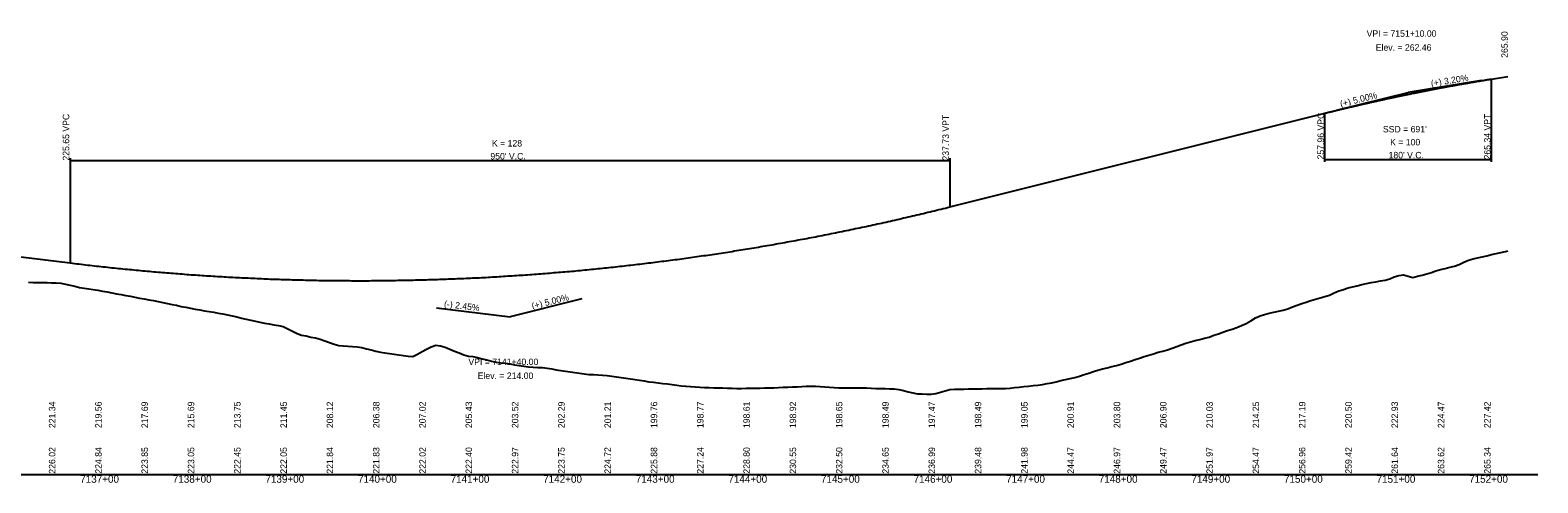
# Model space of a CAD drawing. Extents: x 1838386 to 1955906, y 719739 to 834437.
# Drawn here: x 1897153 to 1898782, y 770980 to 771469 of the extents above; entities that cross this region are included whole.
import ezdxf

# ---------------------------------------------------------------- set-up
doc = ezdxf.new("R2010")
doc.units = 0
for name, color, linetype in [('RD_DDB_GradeTX', 7, 'Continuous'), ('RD_DDB_Profile_EX', 7, 'Continuous'), ('RD_DDB_Profile_Lbl', 7, 'Continuous'), ('RD_DDB_Profile_PR', 7, 'Continuous'), ('RD_DDB_StaTX', 7, 'Continuous'), ('RD_DDB_StripGrade', 7, 'Continuous'), ('RD_DDB_VCLbl', 7, 'Continuous'), ('RD_GPK_Profile_Cell', 7, 'Continuous')]:
    doc.layers.add(name, color=color, linetype=linetype)

msp = doc.modelspace()

# ---------------------------------------------------------------- linework, layer by layer
at = {"layer": 'RD_DDB_GradeTX'}
for p, q in [((1898720.6, 771414.1), (1898641.6, 771401.4)), ((1898564, 771382.1), (1898641.6, 771401.4)), ((1897592.2, 771168.9), (1897671.6, 771159.1)), ((1897749.2, 771178.5), (1897671.6, 771159.1))]:
    msp.add_line(p, q, dxfattribs=at)
at = {"layer": 'RD_DDB_Profile_EX'}
for points in [[(1898226.6, 771083.9), (1898231.6, 771084.4), (1898236.6, 771084.9), (1898241.6, 771085.4), (1898246.6, 771086.3), (1898251.6, 771087.2), (1898256.6, 771088.1), (1898261.6, 771089.2), (1898266.6, 771090.3), (1898271.6, 771091.4), (1898276.6, 771092.6), (1898281.6, 771093.7), (1898286.6, 771095.2), (1898291.6, 771096.9), (1898296.6, 771098.5), (1898301.6, 771100), (1898306.6, 771101.5), (1898311.6, 771102.9), (1898316.6, 771104.2), (1898321.6, 771105.4), (1898326.6, 771106.6), (1898331.6, 771108.2), (1898336.6, 771109.9), (1898341.6, 771111.5), (1898346.6, 771113), (1898351.6, 771114.5), (1898356.6, 771116.2), (1898361.6, 771117.8), (1898366.6, 771119.4), (1898371.6, 771120.9), (1898376.6, 771122.3), (1898381.6, 771123.7), (1898386.6, 771125.4), (1898391.6, 771127.2), (1898396.6, 771128.9), (1898401.6, 771130.6), (1898406.6, 771132.2), (1898411.6, 771133.6), (1898416.6, 771134.8), (1898421.6, 771136), (1898426.6, 771137.4), (1898431.6, 771139.3), (1898436.6, 771141), (1898441.6, 771142.7), (1898446.6, 771144.4), (1898451.6, 771145.9), (1898456.6, 771147.7), (1898461.6, 771149.9), (1898466.6, 771152), (1898471.6, 771154.9), (1898476.6, 771158.1), (1898481.6, 771160.4), (1898486.6, 771161.7), (1898491.6, 771163), (1898496.6, 771164.2), (1898501.6, 771165.4), (1898506.6, 771166.5), (1898511.6, 771167.9), (1898516.6, 771169.9), (1898521.6, 771171.8), (1898526.6, 771173.5), (1898531.6, 771175.1), (1898536.6, 771176.7), (1898541.6, 771178.2), (1898546.6, 771179.6), (1898551.6, 771181), (1898556.6, 771182.5), (1898561.6, 771184.9), (1898566.6, 771187.1), (1898571.6, 771188.7), (1898576.6, 771190.3), (1898581.6, 771191.6), (1898586.6, 771192.8), (1898591.6, 771194), (1898596.6, 771195.1), (1898601.6, 771196.1), (1898606.6, 771197.1), (1898611.6, 771198), (1898616.6, 771198.9), (1898621.6, 771200.2), (1898626.6, 771202.2), (1898631.6, 771203.8), (1898636.6, 771204.6), (1898641.6, 771202.9), (1898646.6, 771201.7), (1898651.6, 771203), (1898656.6, 771204.3), (1898661.6, 771205.5), (1898666.6, 771207.1), (1898671.6, 771208.8), (1898676.6, 771210.4), (1898681.6, 771211.5), (1898686.6, 771212.6), (1898691.6, 771213.8), (1898696.6, 771215.8), (1898701.6, 771218.2), (1898706.6, 771220.5), (1898711.6, 771221.6), (1898716.6, 771222.8), (1898721.6, 771223.9), (1898726.6, 771225.1)], [(1898726.6, 771225.1), (1898731.6, 771226.3), (1898736.6, 771227.4), (1898741.6, 771228.6), (1898746.6, 771229.7), (1898749.2, 771230.3)], [(1897151.6, 771196.5), (1897156.6, 771196.4), (1897161.6, 771196.3), (1897166.6, 771196.2), (1897171.6, 771196.1), (1897176.6, 771196), (1897181.6, 771195.8), (1897186.6, 771195.4), (1897191.6, 771194.4), (1897196.6, 771193.3), (1897201.6, 771192.1), (1897206.6, 771191), (1897211.6, 771190.2), (1897216.6, 771189.5), (1897221.6, 771188.6), (1897226.6, 771187.8)], [(1897226.6, 771187.8), (1897231.6, 771186.9), (1897236.6, 771186), (1897241.6, 771185.1), (1897246.6, 771184.1), (1897251.6, 771183.2), (1897256.6, 771182.2), (1897261.6, 771181.3), (1897266.6, 771180.3), (1897271.6, 771179.3), (1897276.6, 771178.5), (1897281.6, 771177.6), (1897286.6, 771176.7), (1897291.6, 771175.8), (1897296.6, 771174.8), (1897301.6, 771173.7), (1897306.6, 771172.6), (1897311.6, 771171.6), (1897316.6, 771170.5), (1897321.6, 771169.5), (1897326.6, 771168.5), (1897331.6, 771167.6), (1897336.6, 771166.6), (1897341.6, 771165.8), (1897346.6, 771165), (1897351.6, 771164.1), (1897356.6, 771163.3), (1897361.6, 771162.3), (1897366.6, 771161.3), (1897371.6, 771160.1), (1897376.6, 771159), (1897381.6, 771157.9), (1897386.6, 771156.7), (1897391.6, 771155.6), (1897396.6, 771154.4), (1897401.6, 771153.4), (1897406.6, 771152.4), (1897411.6, 771151.5), (1897416.6, 771150.6), (1897421.6, 771149.7), (1897426.6, 771148.9), (1897431.6, 771146.4), (1897436.6, 771143.8), (1897441.6, 771141.2), (1897446.6, 771139.5), (1897451.6, 771138.5), (1897456.6, 771137.4), (1897461.6, 771136.4), (1897466.6, 771135.1), (1897471.6, 771133.3), (1897476.6, 771131.5), (1897481.6, 771129.7), (1897486.6, 771128.2), (1897491.6, 771127.8), (1897496.6, 771127.4), (1897501.6, 771127), (1897506.6, 771126.7), (1897511.6, 771126.1), (1897516.6, 771124.8), (1897521.6, 771123.5), (1897526.6, 771122.3), (1897531.6, 771121), (1897536.6, 771120.3), (1897541.6, 771119.6), (1897546.6, 771118.9), (1897551.6, 771118.2), (1897556.6, 771117.5), (1897561.6, 771116.8), (1897566.6, 771116.5), (1897571.6, 771119), (1897576.6, 771121.6), (1897581.6, 771124.2), (1897586.6, 771126.9), (1897591.6, 771128.5), (1897596.6, 771128), (1897601.6, 771126.4), (1897606.6, 771124.4), (1897611.6, 771122.3), (1897616.6, 771120.3), (1897621.6, 771118.3), (1897626.6, 771116.7), (1897631.6, 771116.3), (1897636.6, 771115.2), (1897641.6, 771114), (1897646.6, 771112.7), (1897651.6, 771111.5), (1897656.6, 771110.3), (1897661.6, 771109.5), (1897666.6, 771109), (1897671.6, 771108.3), (1897676.6, 771107.5), (1897681.6, 771106.8), (1897686.6, 771106), (1897691.6, 771105.3), (1897696.6, 771104.9), (1897701.6, 771104.6), (1897706.6, 771104.4), (1897711.6, 771103.6), (1897716.6, 771102.9), (1897721.6, 771102.1), (1897726.6, 771101.4)], [(1897726.6, 771101.4), (1897731.6, 771100.6), (1897736.6, 771099.9), (1897741.6, 771099.1), (1897746.6, 771098.3), (1897751.6, 771097.6), (1897756.6, 771097), (1897761.6, 771096.8), (1897766.6, 771096.5), (1897771.6, 771096.3), (1897776.6, 771095.9), (1897781.6, 771095.2), (1897786.6, 771094.4), (1897791.6, 771093.7), (1897796.6, 771093), (1897801.6, 771092.2), (1897806.6, 771091.5), (1897811.6, 771090.7), (1897816.6, 771090), (1897821.6, 771089.2), (1897826.6, 771088.6), (1897831.6, 771087.9), (1897836.6, 771087.3), (1897841.6, 771086.7), (1897846.6, 771086), (1897851.6, 771085.4), (1897856.6, 771084.7), (1897861.6, 771084.2), (1897866.6, 771083.9), (1897871.6, 771083.6), (1897876.6, 771083.3), (1897881.6, 771083), (1897886.6, 771082.8), (1897891.6, 771082.6), (1897896.6, 771082.5), (1897901.6, 771082.4), (1897906.6, 771082.2), (1897911.6, 771082.1), (1897916.6, 771082), (1897921.6, 771082), (1897926.6, 771082.1), (1897931.6, 771082.2), (1897936.6, 771082.3), (1897941.6, 771082.3), (1897946.6, 771082.4), (1897951.6, 771082.5), (1897956.6, 771082.7), (1897961.6, 771082.9), (1897966.6, 771083.1), (1897971.6, 771083.3), (1897976.6, 771083.5), (1897981.6, 771083.8), (1897986.6, 771084), (1897991.6, 771084.2), (1897996.6, 771084.4), (1898001.6, 771084.5), (1898006.6, 771084.1), (1898011.6, 771083.7), (1898016.6, 771083.3), (1898021.6, 771083), (1898026.6, 771082.6), (1898031.6, 771082.4), (1898036.6, 771082.4), (1898041.6, 771082.4), (1898046.6, 771082.4), (1898051.6, 771082.4), (1898056.6, 771082.4), (1898061.6, 771082.2), (1898066.6, 771082), (1898071.6, 771081.9), (1898076.6, 771081.7), (1898081.6, 771081.6), (1898086.6, 771081.4), (1898091.6, 771080.8), (1898096.6, 771079.6), (1898101.6, 771078.3), (1898106.6, 771077.1), (1898111.6, 771076), (1898116.6, 771075.9), (1898121.6, 771075.8), (1898126.6, 771075.7), (1898131.6, 771076.5), (1898136.6, 771077.9), (1898141.6, 771079.3), (1898146.6, 771080.6), (1898151.6, 771081), (1898156.6, 771081.1), (1898161.6, 771081.2), (1898166.6, 771081.3), (1898171.6, 771081.4), (1898176.6, 771081.5), (1898181.6, 771081.6), (1898186.6, 771081.7), (1898191.6, 771081.8), (1898196.6, 771081.9), (1898201.6, 771081.9), (1898206.6, 771082), (1898211.6, 771082.3), (1898216.6, 771082.8), (1898221.6, 771083.3), (1898226.6, 771083.9)]]:
    msp.add_lwpolyline(points, dxfattribs=at)
at = {"layer": 'RD_DDB_Profile_PR'}
for p, q in [((1898731.6, 771415.8), (1898749.2, 771418.7)), ((1898146.6, 771277.8), (1898551.6, 771379)), ((1896959.1, 771246.5), (1897196.6, 771217.4))]:
    msp.add_line(p, q, dxfattribs=at)
for points in [[(1898551.6, 771379), (1898555.2, 771379.9), (1898558.8, 771380.7), (1898562.4, 771381.6), (1898566, 771382.5), (1898569.6, 771383.4), (1898573.2, 771384.2), (1898576.8, 771385.1), (1898580.4, 771385.9), (1898584, 771386.8), (1898587.6, 771387.6), (1898591.2, 771388.5), (1898594.8, 771389.3), (1898598.4, 771390.1), (1898602, 771390.9), (1898605.6, 771391.7), (1898609.2, 771392.5), (1898612.8, 771393.3), (1898616.4, 771394.1), (1898620, 771394.9), (1898623.6, 771395.7), (1898627.2, 771396.4), (1898630.8, 771397.2), (1898634.4, 771397.9), (1898638, 771398.7), (1898641.6, 771399.4), (1898645.2, 771400.2), (1898648.8, 771400.9), (1898652.4, 771401.6), (1898656, 771402.3), (1898659.6, 771403), (1898663.2, 771403.7), (1898666.8, 771404.4), (1898670.4, 771405.1), (1898674, 771405.8), (1898677.6, 771406.5), (1898681.2, 771407.1), (1898684.8, 771407.8), (1898688.4, 771408.5), (1898692, 771409.1), (1898695.6, 771409.8), (1898699.2, 771410.4), (1898702.8, 771411), (1898706.4, 771411.7), (1898710, 771412.3), (1898713.6, 771412.9), (1898717.2, 771413.5), (1898720.8, 771414.1), (1898724.4, 771414.7), (1898728, 771415.3), (1898731.6, 771415.8)], [(1897196.6, 771217.4), (1897215.6, 771215.1), (1897234.6, 771213), (1897253.6, 771211), (1897272.6, 771209.2), (1897291.6, 771207.5), (1897310.6, 771206), (1897329.6, 771204.5), (1897348.6, 771203.3), (1897367.6, 771202.1), (1897386.6, 771201.2), (1897405.6, 771200.3), (1897424.6, 771199.6), (1897443.6, 771199.1), (1897462.6, 771198.6), (1897481.6, 771198.4), (1897500.6, 771198.2), (1897519.6, 771198.2), (1897538.6, 771198.4), (1897557.6, 771198.7), (1897576.6, 771199.1), (1897595.6, 771199.7), (1897614.6, 771200.4), (1897633.6, 771201.2), (1897652.6, 771202.2), (1897671.6, 771203.4), (1897690.6, 771204.6), (1897709.6, 771206.1), (1897728.6, 771207.6), (1897747.6, 771209.3), (1897766.6, 771211.2), (1897785.6, 771213.2), (1897804.6, 771215.3), (1897823.6, 771217.6), (1897842.6, 771220), (1897861.6, 771222.5), (1897880.6, 771225.2), (1897899.6, 771228), (1897918.6, 771231), (1897937.6, 771234.1), (1897956.6, 771237.4), (1897975.6, 771240.8), (1897994.6, 771244.3), (1898013.6, 771248), (1898032.6, 771251.9), (1898051.6, 771255.8), (1898070.6, 771259.9), (1898089.6, 771264.2), (1898108.6, 771268.6), (1898127.6, 771273.1), (1898146.6, 771277.8)]]:
    msp.add_spline(points, degree=3, dxfattribs=at)
at = {"layer": 'RD_DDB_VCLbl'}
for p, q in [((1898731.6, 771326.5), (1898731.6, 771415.8)), ((1898551.6, 771326.5), (1898551.6, 771379)), ((1897196.6, 771330.3), (1897196.6, 771217.4)), ((1898146.6, 771330.3), (1898146.6, 771277.8)), ((1898551.6, 771329), (1898731.6, 771329)), ((1897196.6, 771327.8), (1898146.6, 771327.8))]:
    msp.add_line(p, q, dxfattribs=at)
at = {"layer": 'RD_GPK_Profile_Cell'}
msp.add_line((1895681.6, 770989.1), (1898781.6, 770989.1), dxfattribs=at)

# ---------------------------------------------------------------- texts
at = {"layer": 'RD_DDB_GradeTX'}
for s, rotation, p in [('(+) 3.20%', 9.0903, (1898666.7, 771407.5)), ('(+) 5.00%', 14.0256, (1898569, 771385.4)), ('(+) 5.00%', 14.0256, (1897696, 771167.3)), ('(-) 2.45%', 353.0082, (1897600.1, 771169.9))]:
    msp.add_text(s, height=7, rotation=rotation, dxfattribs=at).set_placement(p)
at = {"layer": 'RD_DDB_Profile_Lbl'}
for s, p in [('VPI = 7151+10.00', (1898596.7, 771461.4)), ('Elev. = 262.46', (1898606.6, 771446.4)), ('VPI = 7141+40.00', (1897626.7, 771107.1)), ('Elev. = 214.00', (1897636.7, 771092.1))]:
    msp.add_text(s, height=7, dxfattribs=at).set_placement(p)
msp.add_text('265.90', height=7, rotation=90, dxfattribs=at).set_placement((1898749.2, 771438.7))
at = {"layer": 'RD_DDB_StaTX'}
for s, p in [('7137+00', (1897207.4, 770980.1)), ('7138+00', (1897307.4, 770980.1)), ('7139+00', (1897407.4, 770980.1)), ('7140+00', (1897507.4, 770980.1)), ('7141+00', (1897607.4, 770980.1)), ('7142+00', (1897707.4, 770980.1)), ('7143+00', (1897807.4, 770980.1)), ('7144+00', (1897907.4, 770980.1)), ('7145+00', (1898007.4, 770980.1)), ('7146+00', (1898107.4, 770980.1)), ('7147+00', (1898207.4, 770980.1)), ('7148+00', (1898307.4, 770980.1)), ('7149+00', (1898407.4, 770980.1)), ('7150+00', (1898507.4, 770980.1)), ('7151+00', (1898607.4, 770980.1)), ('7152+00', (1898707.4, 770980.1))]:
    msp.add_text(s, height=8, dxfattribs=at).set_placement(p)
at = {"layer": 'RD_DDB_StripGrade'}
for s, p in [('225.65 VPC', (1897195.6, 771327.8)), ('257.96 VPC', (1898550.6, 771329)), ('265.34 VPT', (1898730.6, 771329)), ('237.73 VPT', (1898145.6, 771327.8)), ('221.34', (1897180.6, 771039.1)), ('219.56', (1897230.6, 771039.1)), ('217.69', (1897280.6, 771039.1)), ('215.69', (1897330.6, 771039.1)), ('213.75', (1897380.6, 771039.1)), ('211.45', (1897430.6, 771039.1)), ('208.12', (1897480.6, 771039.1)), ('206.38', (1897530.6, 771039.1)), ('207.02', (1897580.6, 771039.1)), ('205.43', (1897630.6, 771039.1)), ('203.52', (1897680.6, 771039.1)), ('202.29', (1897730.6, 771039.1)), ('201.21', (1897780.6, 771039.1)), ('199.76', (1897830.6, 771039.1)), ('198.77', (1897880.6, 771039.1)), ('198.61', (1897930.6, 771039.1)), ('198.92', (1897980.6, 771039.1)), ('198.65', (1898030.6, 771039.1)), ('198.49', (1898080.6, 771039.1)), ('197.47', (1898130.6, 771039.1)), ('198.49', (1898180.6, 771039.1)), ('199.05', (1898230.6, 771039.1)), ('200.91', (1898280.6, 771039.1)), ('203.80', (1898330.6, 771039.1)), ('206.90', (1898380.6, 771039.1)), ('210.03', (1898430.6, 771039.1)), ('214.25', (1898480.6, 771039.1)), ('217.19', (1898530.6, 771039.1)), ('220.50', (1898580.6, 771039.1)), ('222.93', (1898630.6, 771039.1)), ('224.47', (1898680.6, 771039.1)), ('227.42', (1898730.6, 771039.1)), ('226.02', (1897180.6, 770989.9)), ('224.84', (1897230.6, 770989.9)), ('223.85', (1897280.6, 770989.9)), ('223.05', (1897330.6, 770989.9)), ('222.45', (1897380.6, 770989.9)), ('222.05', (1897430.6, 770989.9)), ('221.84', (1897480.6, 770989.9)), ('221.83', (1897530.6, 770989.9)), ('222.02', (1897580.6, 770989.9)), ('222.40', (1897630.6, 770989.9)), ('222.97', (1897680.6, 770989.9)), ('223.75', (1897730.6, 770989.9)), ('224.72', (1897780.6, 770989.9)), ('225.88', (1897830.6, 770989.9)), ('227.24', (1897880.6, 770989.9)), ('228.80', (1897930.6, 770989.9)), ('230.55', (1897980.6, 770989.9)), ('232.50', (1898030.6, 770989.9)), ('234.65', (1898080.6, 770989.9)), ('236.99', (1898130.6, 770989.9)), ('239.48', (1898180.6, 770989.9)), ('241.98', (1898230.6, 770989.9)), ('244.47', (1898280.6, 770989.9)), ('246.97', (1898330.6, 770989.9)), ('249.47', (1898380.6, 770989.9)), ('251.97', (1898430.6, 770989.9)), ('254.47', (1898480.6, 770989.9)), ('256.96', (1898530.6, 770989.9)), ('259.42', (1898580.6, 770989.9)), ('261.64', (1898630.6, 770989.9)), ('263.62', (1898680.6, 770989.9)), ('265.34', (1898730.6, 770989.9))]:
    msp.add_text(s, height=7, rotation=90, dxfattribs=at).set_placement(p)
at = {"layer": 'RD_DDB_VCLbl'}
for s, p in [("SSD = 691'", (1898614.3, 771358.2)), ('K = 128', (1897652.1, 771343)), ('K = 100', (1898622.1, 771344.2)), ("950' V.C.", (1897650.4, 771329)), ("180' V.C.", (1898620.4, 771330.2))]:
    msp.add_text(s, height=7, dxfattribs=at).set_placement(p)

doc.saveas('drawing.dxf')
